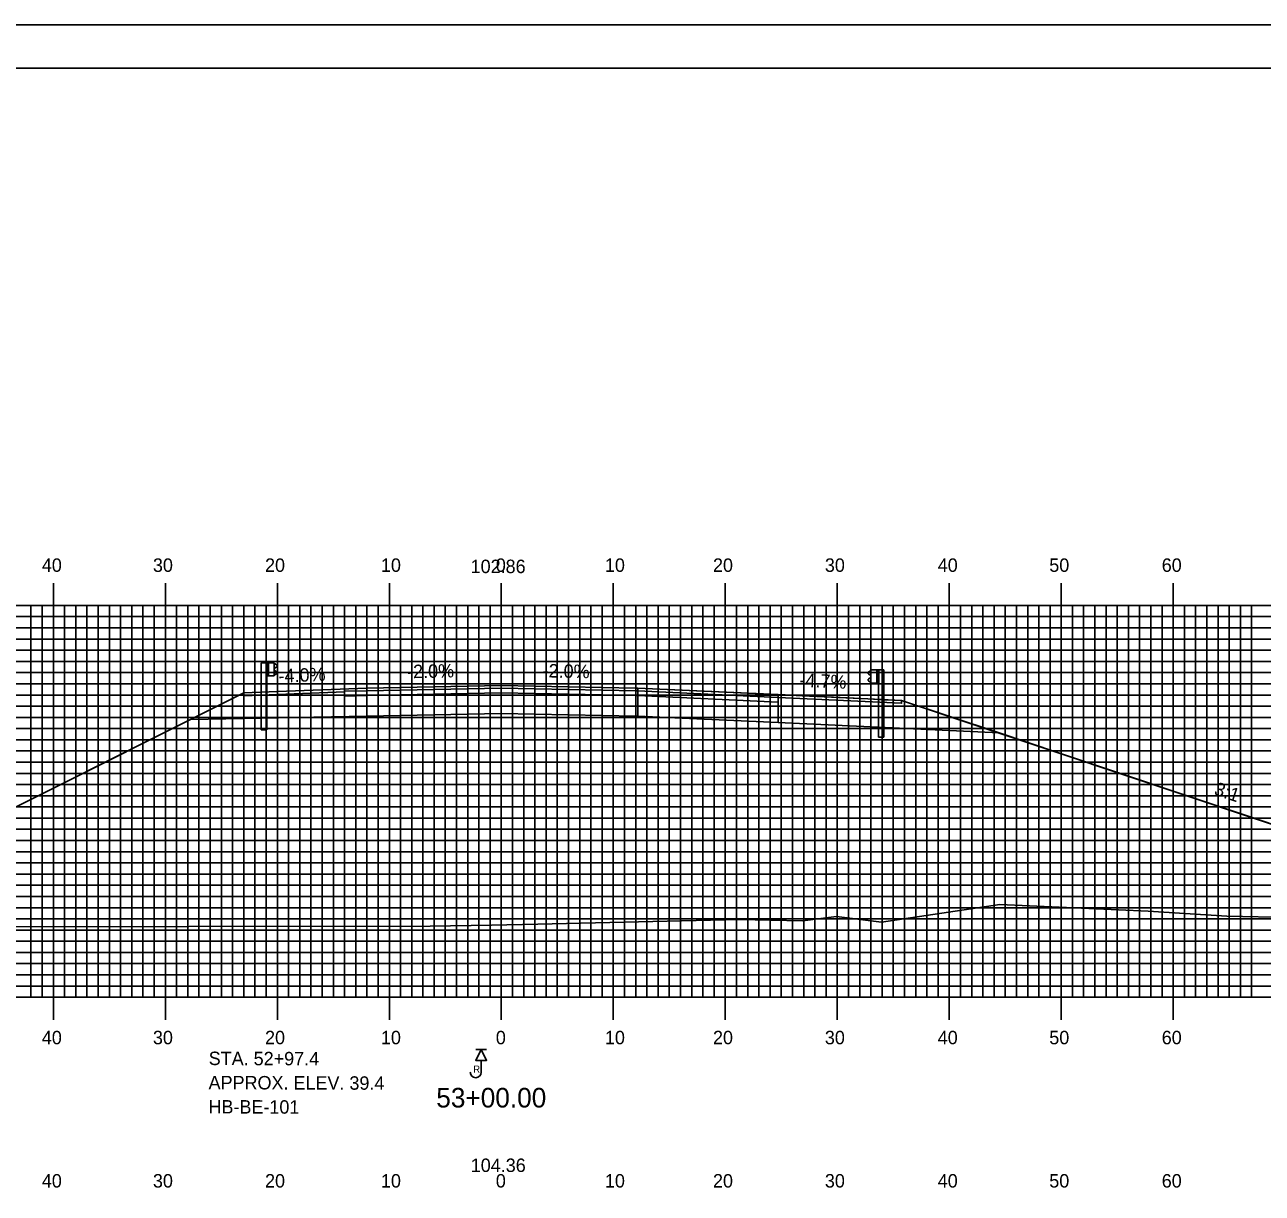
# Model space of a CAD drawing. Extents: x 1755888 to 1756232, y 442591 to 442811.
# Drawn here: x 1756011.5 to 1756122, y 442706.2 to 442810.5 of the extents above; entities that cross this region are included whole.
import ezdxf

# ---------------------------------------------------------------- set-up
doc = ezdxf.new("R2010")
doc.units = 0
for name, color, linetype in [('ANNOTATION', 7, 'Continuous'), ('BORDER', 7, 'Continuous'), ('BORING - REFUSAL', 7, 'Continuous'), ('D_Guardrail_Beam_Lt', 7, 'Continuous'), ('D_Guardrail_Beam_Rt', 7, 'Continuous'), ('D_Roadway_Centerline', 7, 'Continuous'), ('D_Roadway_Centerline_Text', 7, 'Continuous'), ('D_Roadway_Edge_Shoulder', 7, 'Continuous'), ('D_Roadway_Edge_TW', 7, 'Continuous'), ('D_Roadway_Pavement', 7, 'Continuous'), ('D_Roadway_SlopeLines', 7, 'Continuous'), ('D_Roadway_SubGrade', 7, 'Continuous'), ('H_V ANNOTATION', 7, 'Continuous'), ('MAJOR', 7, 'Continuous'), ('MINOR', 7, 'Continuous'), ('PLOT BOUNDARY', 7, 'Continuous'), ('S_Roadway_Centerline', 7, 'Continuous')]:
    doc.layers.add(name, color=color, linetype=linetype)

msp = doc.modelspace()

# ---------------------------------------------------------------- linework, layer by layer
at = {"layer": 'BORDER'}
msp.add_lwpolyline([(1755904.46, 442596.67), (1756224.46, 442596.67), (1756224.46, 442806.67), (1755904.46, 442806.67)], close=True, dxfattribs=at)
at = {"layer": 'BORING - REFUSAL'}
for p, q in [((1756052.74, 442718.99), (1756051.78, 442718.99)), ((1756052.26, 442718.03), (1756052.26, 442716.97))]:
    msp.add_line(p, q, dxfattribs=at)
msp.add_lwpolyline([(1756052.26, 442718.99), (1756052.74, 442718.03), (1756051.78, 442718.03)], close=True, dxfattribs=at)
msp.add_arc((1756051.77, 442716.97), 0.485, 180, 0, dxfattribs=at)
at = {"layer": 'D_Guardrail_Beam_Lt'}
for p, q in [((1756032.63, 442753.55), (1756032.63, 442747.55)), ((1756033.1, 442753.55), (1756032.63, 442753.55)), ((1756033.79, 442753.55), (1756033.1, 442753.55)), ((1756033.1, 442753.55), (1756033.1, 442752.38)), ((1756033.16, 442753.55), (1756033.16, 442752.38)), ((1756033.27, 442753.55), (1756033.27, 442752.38)), ((1756033.79, 442752.38), (1756033.79, 442753.55)), ((1756033.79, 442753.47), (1756033.86, 442753.45)), ((1756034.02, 442753.2), (1756033.82, 442753.07)), ((1756033.88, 442753.45), (1756034.02, 442753.35)), ((1756033.1, 442752.38), (1756033.79, 442752.38)), ((1756033.12, 442747.55), (1756033.12, 442752.38)), ((1756033.79, 442753), (1756033.79, 442752.93)), ((1756033.86, 442752.48), (1756033.79, 442752.47)), ((1756033.82, 442752.87), (1756034.02, 442752.73)), ((1756034.02, 442752.59), (1756033.88, 442752.49)), ((1756033.12, 442747.55), (1756032.63, 442747.55))]:
    msp.add_line(p, q, dxfattribs=at)
for centre, major_axis, start_param, end_param in [((1756033.87, 442753), (-0.0789, 0), 5.323254, 6.283185), ((1756033.85, 442753.41), (0.0417, 0), 0.959931, 1.376053), ((1756033.97, 442753.28), (0.0877, 0), 5.323254, 7.243116), ((1756033.87, 442752.93), (-0.0789, 0), 6.283185, 7.243116), ((1756033.85, 442752.52), (0.0417, 0), 4.907132, 5.323254), ((1756033.97, 442752.66), (0.0877, 0), 5.323254, 7.243116)]:
    msp.add_ellipse(centre, major_axis=major_axis, ratio=0.995501, start_param=start_param, end_param=end_param, dxfattribs=at)
at = {"layer": 'D_Guardrail_Beam_Rt'}
for p, q in [((1756086.98, 442752.8), (1756086.84, 442752.7)), ((1756086.84, 442752.56), (1756087.03, 442752.42)), ((1756087.03, 442752.23), (1756086.84, 442752.09)), ((1756086.84, 442751.95), (1756086.98, 442751.85)), ((1756087.07, 442752.82), (1756086.99, 442752.81)), ((1756087.06, 442752.36), (1756087.06, 442752.29)), ((1756087.07, 442752.91), (1756087.76, 442752.91)), ((1756087.07, 442751.74), (1756087.07, 442752.91)), ((1756087.59, 442752.91), (1756087.59, 442751.74)), ((1756087.69, 442752.91), (1756087.69, 442751.74)), ((1756087.76, 442752.91), (1756088.23, 442752.91)), ((1756087.76, 442752.91), (1756087.76, 442751.74)), ((1756088.23, 442752.91), (1756088.23, 442746.91)), ((1756086.99, 442751.84), (1756087.07, 442751.82)), ((1756087.76, 442751.74), (1756087.07, 442751.74)), ((1756087.74, 442746.91), (1756087.74, 442751.74)), ((1756087.74, 442746.91), (1756088.23, 442746.91))]:
    msp.add_line(p, q, dxfattribs=at)
for centre, major_axis, start_param, end_param in [((1756086.89, 442752.63), (-0.0877, 0), 5.323254, 7.243116), ((1756086.89, 442752.02), (-0.0877, 0), 5.323254, 7.243116), ((1756087, 442752.77), (-0.0417, 0), 4.907132, 5.323254), ((1756086.99, 442752.36), (0.0789, 0), 0, 0.959931), ((1756086.99, 442752.29), (0.0789, 0), 5.323254, 6.283185), ((1756087, 442751.88), (-0.0417, 0), 0.959931, 1.376053)]:
    msp.add_ellipse(centre, major_axis=major_axis, ratio=0.995501, start_param=start_param, end_param=end_param, dxfattribs=at)
at = {"layer": 'D_Roadway_Centerline'}
msp.add_lwpolyline([(1755989.06, 442729.85), (1756026.31, 442748.47), (1756031.06, 442750.85), (1756034.06, 442750.97), (1756042.06, 442751.29), (1756054.06, 442751.53), (1756066.06, 442751.29), (1756066.24, 442751.28), (1756076.73, 442750.8), (1756078.79, 442750.7), (1756080.93, 442750.6), (1756086.8, 442750.32), (1756088.3, 442750.25), (1756089.8, 442750.18), (1756096.45, 442747.96), (1756098.5, 442747.28), (1756103.73, 442745.53), (1756120.4, 442739.96), (1756133.71, 442735.51), (1756138.61, 442733.87), (1756146.45, 442731.25)], dxfattribs=at)
at = {"layer": 'D_Roadway_Edge_Shoulder'}
for points in [[(1756042.06, 442751.29), (1756034.06, 442750.97), (1756034.06, 442750.97), (1756031.06, 442750.85), (1756031.06, 442750.6), (1756040.06, 442750.96), (1756040.06, 442751), (1756042.06, 442751.04)], [(1756078.79, 442750.7), (1756086.8, 442750.32), (1756086.8, 442750.32), (1756089.8, 442750.18), (1756089.8, 442749.93), (1756078.79, 442750.45)]]:
    msp.add_lwpolyline(points, close=True, dxfattribs=at)
at = {"layer": 'D_Roadway_Edge_TW'}
for points in [[(1756042.06, 442751.04), (1756042.06, 442751.29), (1756054.06, 442751.53), (1756066.06, 442751.29), (1756066.06, 442751.04), (1756054.06, 442751.28)], [(1756066.06, 442751.29), (1756066.24, 442751.28), (1756066.24, 442751.03), (1756066.06, 442751.04)], [(1756066.24, 442751.28), (1756078.79, 442750.7), (1756078.79, 442750.45), (1756066.24, 442751.03)]]:
    msp.add_lwpolyline(points, close=True, dxfattribs=at)
at = {"layer": 'D_Roadway_Pavement'}
for points in [[(1756042.06, 442751.04), (1756040.06, 442751), (1756040.06, 442750.96), (1756040.06, 442750.58), (1756042.06, 442750.62)], [(1756042.06, 442750.62), (1756042.06, 442751.04), (1756054.06, 442751.28), (1756066.06, 442751.04), (1756066.06, 442750.62), (1756054.06, 442750.86)], [(1756066.06, 442751.04), (1756066.24, 442751.03), (1756066.24, 442750.62), (1756066.06, 442750.62)], [(1756066.24, 442751.03), (1756078.79, 442750.45), (1756078.79, 442750.03), (1756066.24, 442750.62)]]:
    msp.add_lwpolyline(points, close=True, dxfattribs=at)
msp.add_lwpolyline([(1756078.79, 442750.45), (1756078.79, 442750.03)], dxfattribs=at)
msp.add_lwpolyline([(1756078.79, 442750.45), (1756078.79, 442750.03)], dxfattribs=at)
at = {"layer": 'D_Roadway_SlopeLines'}
for points in [[(1756031.06, 442750.85), (1755989.06, 442729.85)], [(1756089.8, 442750.18), (1756146.45, 442731.25)]]:
    msp.add_lwpolyline(points, dxfattribs=at)
at = {"layer": 'D_Roadway_SubGrade'}
for points in [[(1756042.06, 442750.62), (1756040.06, 442750.58), (1756040.06, 442750.96), (1756031.06, 442750.6), (1756031.06, 442750.85), (1756026.31, 442748.47), (1756042.06, 442748.79)], [(1756042.06, 442748.79), (1756042.06, 442750.62), (1756054.06, 442750.86), (1756066.06, 442750.62), (1756066.06, 442748.79), (1756054.06, 442749.03)], [(1756066.06, 442750.62), (1756066.24, 442750.62), (1756066.24, 442748.78), (1756066.06, 442748.79)], [(1756066.24, 442750.62), (1756078.79, 442750.03), (1756078.79, 442748.2), (1756066.24, 442748.78)], [(1756078.79, 442750.03), (1756078.79, 442750.45), (1756089.8, 442749.93), (1756089.8, 442750.18), (1756098.5, 442747.28), (1756078.79, 442748.2)]]:
    msp.add_lwpolyline(points, close=True, dxfattribs=at)
at = {"layer": 'MAJOR'}
for p, q in [((1756014.06, 442760.67), (1756014.06, 442758.67)), ((1756024.06, 442760.67), (1756024.06, 442758.67)), ((1756034.06, 442760.67), (1756034.06, 442758.67)), ((1756044.06, 442760.67), (1756044.06, 442758.67)), ((1756054.06, 442760.67), (1756054.06, 442758.67)), ((1756064.06, 442760.67), (1756064.06, 442758.67)), ((1756074.06, 442760.67), (1756074.06, 442758.67)), ((1756084.06, 442760.67), (1756084.06, 442758.67)), ((1756094.06, 442760.67), (1756094.06, 442758.67)), ((1756104.06, 442760.67), (1756104.06, 442758.67)), ((1756114.06, 442760.67), (1756114.06, 442758.67)), ((1755914.06, 442758.67), (1756194.06, 442758.67)), ((1755914.06, 442758.67), (1756194.06, 442758.67)), ((1756014.06, 442723.67), (1756014.06, 442758.67)), ((1756024.06, 442723.67), (1756024.06, 442758.67)), ((1756034.06, 442723.67), (1756034.06, 442758.67)), ((1756044.06, 442723.67), (1756044.06, 442758.67)), ((1756054.06, 442723.67), (1756054.06, 442758.67)), ((1756064.06, 442723.67), (1756064.06, 442758.67)), ((1756074.06, 442723.67), (1756074.06, 442758.67)), ((1756084.06, 442723.67), (1756084.06, 442758.67)), ((1756094.06, 442723.67), (1756094.06, 442758.67)), ((1756104.06, 442723.67), (1756104.06, 442758.67)), ((1756114.06, 442723.67), (1756114.06, 442758.67)), ((1755914.06, 442753.67), (1756194.06, 442753.67)), ((1755914.06, 442748.67), (1756194.06, 442748.67)), ((1755914.06, 442743.67), (1756194.06, 442743.67)), ((1755914.06, 442738.67), (1756194.06, 442738.67)), ((1755914.06, 442733.67), (1756194.06, 442733.67)), ((1755914.06, 442728.67), (1756194.06, 442728.67)), ((1755914.06, 442723.67), (1756194.06, 442723.67)), ((1755914.06, 442723.67), (1756194.06, 442723.67)), ((1756014.06, 442721.66), (1756014.06, 442723.67)), ((1756024.06, 442721.66), (1756024.06, 442723.67)), ((1756034.06, 442721.66), (1756034.06, 442723.67)), ((1756044.06, 442721.66), (1756044.06, 442723.67)), ((1756054.06, 442721.66), (1756054.06, 442723.67)), ((1756064.06, 442721.66), (1756064.06, 442723.67)), ((1756074.06, 442721.66), (1756074.06, 442723.67)), ((1756084.06, 442721.66), (1756084.06, 442723.67)), ((1756094.06, 442721.66), (1756094.06, 442723.67)), ((1756104.06, 442721.66), (1756104.06, 442723.67)), ((1756114.06, 442721.66), (1756114.06, 442723.67))]:
    msp.add_line(p, q, dxfattribs=at)
at = {"layer": 'MINOR'}
for p, q in [((1756012.06, 442723.67), (1756012.06, 442758.67)), ((1756013.06, 442723.67), (1756013.06, 442758.67)), ((1756015.06, 442723.67), (1756015.06, 442758.67)), ((1756016.06, 442723.67), (1756016.06, 442758.67)), ((1756017.06, 442723.67), (1756017.06, 442758.67)), ((1756018.06, 442723.67), (1756018.06, 442758.67)), ((1756019.06, 442723.67), (1756019.06, 442758.67)), ((1756020.06, 442723.67), (1756020.06, 442758.67)), ((1756021.06, 442723.67), (1756021.06, 442758.67)), ((1756022.06, 442723.67), (1756022.06, 442758.67)), ((1756023.06, 442723.67), (1756023.06, 442758.67)), ((1756025.06, 442723.67), (1756025.06, 442758.67)), ((1756026.06, 442723.67), (1756026.06, 442758.67)), ((1756027.06, 442723.67), (1756027.06, 442758.67)), ((1756028.06, 442723.67), (1756028.06, 442758.67)), ((1756029.06, 442723.67), (1756029.06, 442758.67)), ((1756030.06, 442723.67), (1756030.06, 442758.67)), ((1756031.06, 442723.67), (1756031.06, 442758.67)), ((1756032.06, 442723.67), (1756032.06, 442758.67)), ((1756033.06, 442723.67), (1756033.06, 442758.67)), ((1756035.06, 442723.67), (1756035.06, 442758.67)), ((1756036.06, 442723.67), (1756036.06, 442758.67)), ((1756037.06, 442723.67), (1756037.06, 442758.67)), ((1756038.06, 442723.67), (1756038.06, 442758.67)), ((1756039.06, 442723.67), (1756039.06, 442758.67)), ((1756040.06, 442723.67), (1756040.06, 442758.67)), ((1756041.06, 442723.67), (1756041.06, 442758.67)), ((1756042.06, 442723.67), (1756042.06, 442758.67)), ((1756043.06, 442723.67), (1756043.06, 442758.67)), ((1756045.06, 442723.67), (1756045.06, 442758.67)), ((1756046.06, 442723.67), (1756046.06, 442758.67)), ((1756047.06, 442723.67), (1756047.06, 442758.67)), ((1756048.06, 442723.67), (1756048.06, 442758.67)), ((1756049.06, 442723.67), (1756049.06, 442758.67)), ((1756050.06, 442723.67), (1756050.06, 442758.67)), ((1756051.06, 442723.67), (1756051.06, 442758.67)), ((1756052.06, 442723.67), (1756052.06, 442758.67)), ((1756053.06, 442723.67), (1756053.06, 442758.67)), ((1756055.06, 442723.67), (1756055.06, 442758.67)), ((1756056.06, 442723.67), (1756056.06, 442758.67)), ((1756057.06, 442723.67), (1756057.06, 442758.67)), ((1756058.06, 442723.67), (1756058.06, 442758.67)), ((1756059.06, 442723.67), (1756059.06, 442758.67)), ((1756060.06, 442723.67), (1756060.06, 442758.67)), ((1756061.06, 442723.67), (1756061.06, 442758.67)), ((1756062.06, 442723.67), (1756062.06, 442758.67)), ((1756063.06, 442723.67), (1756063.06, 442758.67)), ((1756065.06, 442723.67), (1756065.06, 442758.67)), ((1756066.06, 442723.67), (1756066.06, 442758.67)), ((1756067.06, 442723.67), (1756067.06, 442758.67)), ((1756068.06, 442723.67), (1756068.06, 442758.67)), ((1756069.06, 442723.67), (1756069.06, 442758.67)), ((1756070.06, 442723.67), (1756070.06, 442758.67)), ((1756071.06, 442723.67), (1756071.06, 442758.67)), ((1756072.06, 442723.67), (1756072.06, 442758.67)), ((1756073.06, 442723.67), (1756073.06, 442758.67)), ((1756075.06, 442723.67), (1756075.06, 442758.67)), ((1756076.06, 442723.67), (1756076.06, 442758.67)), ((1756077.06, 442723.67), (1756077.06, 442758.67)), ((1756078.06, 442723.67), (1756078.06, 442758.67)), ((1756079.06, 442723.67), (1756079.06, 442758.67)), ((1756080.06, 442723.67), (1756080.06, 442758.67)), ((1756081.06, 442723.67), (1756081.06, 442758.67)), ((1756082.06, 442723.67), (1756082.06, 442758.67)), ((1756083.06, 442723.67), (1756083.06, 442758.67)), ((1756085.06, 442723.67), (1756085.06, 442758.67)), ((1756086.06, 442723.67), (1756086.06, 442758.67)), ((1756087.06, 442723.67), (1756087.06, 442758.67)), ((1756088.06, 442723.67), (1756088.06, 442758.67)), ((1756089.06, 442723.67), (1756089.06, 442758.67)), ((1756090.06, 442723.67), (1756090.06, 442758.67)), ((1756091.06, 442723.67), (1756091.06, 442758.67)), ((1756092.06, 442723.67), (1756092.06, 442758.67)), ((1756093.06, 442723.67), (1756093.06, 442758.67)), ((1756095.06, 442723.67), (1756095.06, 442758.67)), ((1756096.06, 442723.67), (1756096.06, 442758.67)), ((1756097.06, 442723.67), (1756097.06, 442758.67)), ((1756098.06, 442723.67), (1756098.06, 442758.67)), ((1756099.06, 442723.67), (1756099.06, 442758.67)), ((1756100.06, 442723.67), (1756100.06, 442758.67)), ((1756101.06, 442723.67), (1756101.06, 442758.67)), ((1756102.06, 442723.67), (1756102.06, 442758.67)), ((1756103.06, 442723.67), (1756103.06, 442758.67)), ((1756105.06, 442723.67), (1756105.06, 442758.67)), ((1756106.06, 442723.67), (1756106.06, 442758.67)), ((1756107.06, 442723.67), (1756107.06, 442758.67)), ((1756108.06, 442723.67), (1756108.06, 442758.67)), ((1756109.06, 442723.67), (1756109.06, 442758.67)), ((1756110.06, 442723.67), (1756110.06, 442758.67)), ((1756111.06, 442723.67), (1756111.06, 442758.67)), ((1756112.06, 442723.67), (1756112.06, 442758.67)), ((1756113.06, 442723.67), (1756113.06, 442758.67)), ((1756115.06, 442723.67), (1756115.06, 442758.67)), ((1756116.06, 442723.67), (1756116.06, 442758.67)), ((1756117.06, 442723.67), (1756117.06, 442758.67)), ((1756118.06, 442723.67), (1756118.06, 442758.67)), ((1756119.06, 442723.67), (1756119.06, 442758.67)), ((1756120.06, 442723.67), (1756120.06, 442758.67)), ((1756121.06, 442723.67), (1756121.06, 442758.67)), ((1755914.06, 442757.67), (1756194.06, 442757.67)), ((1755914.06, 442756.67), (1756194.06, 442756.67)), ((1755914.06, 442755.67), (1756194.06, 442755.67)), ((1755914.06, 442754.67), (1756194.06, 442754.67)), ((1755914.06, 442752.67), (1756194.06, 442752.67)), ((1755914.06, 442751.67), (1756194.06, 442751.67)), ((1755914.06, 442750.67), (1756194.06, 442750.67)), ((1755914.06, 442749.67), (1756194.06, 442749.67)), ((1755914.06, 442747.67), (1756194.06, 442747.67)), ((1755914.06, 442746.67), (1756194.06, 442746.67)), ((1755914.06, 442745.67), (1756194.06, 442745.67)), ((1755914.06, 442744.67), (1756194.06, 442744.67)), ((1755914.06, 442742.67), (1756194.06, 442742.67)), ((1755914.06, 442741.67), (1756194.06, 442741.67)), ((1755914.06, 442740.67), (1756194.06, 442740.67)), ((1755914.06, 442739.67), (1756194.06, 442739.67)), ((1755914.06, 442737.67), (1756194.06, 442737.67)), ((1755914.06, 442736.67), (1756194.06, 442736.67)), ((1755914.06, 442735.67), (1756194.06, 442735.67)), ((1755914.06, 442734.67), (1756194.06, 442734.67)), ((1755914.06, 442732.67), (1756194.06, 442732.67)), ((1755914.06, 442731.67), (1756194.06, 442731.67)), ((1755914.06, 442730.67), (1756194.06, 442730.67)), ((1755914.06, 442729.67), (1756194.06, 442729.67)), ((1755914.06, 442727.67), (1756194.06, 442727.67)), ((1755914.06, 442726.67), (1756194.06, 442726.67)), ((1755914.06, 442725.67), (1756194.06, 442725.67)), ((1755914.06, 442724.67), (1756194.06, 442724.67))]:
    msp.add_line(p, q, dxfattribs=at)
at = {"layer": 'PLOT BOUNDARY'}
msp.add_lwpolyline([(1755888.27, 442590.55), (1756228.27, 442590.55), (1756228.27, 442810.55), (1755888.27, 442810.55)], close=True, dxfattribs=at)
at = {"layer": 'S_Roadway_Centerline'}
msp.add_lwpolyline([(1755914.06, 442729.3), (1755929.02, 442728.93), (1755936.66, 442728.91), (1755939.99, 442729.1), (1755959.43, 442728.85), (1755985.74, 442729.81), (1755998.98, 442729.96), (1756004.62, 442729.97), (1756047.7, 442730.01), (1756053.19, 442730.1), (1756057.32, 442730.2), (1756075.29, 442730.61), (1756080.95, 442730.51), (1756083.99, 442730.88), (1756088.01, 442730.38), (1756098.56, 442731.95), (1756111.81, 442731.35), (1756118.83, 442730.91), (1756130.1, 442730.66), (1756146.83, 442731.27), (1756164.74, 442730.34), (1756179.2, 442730.36), (1756189.71, 442730.46), (1756194.06, 442730.48)], dxfattribs=at)

# ---------------------------------------------------------------- texts
at = {"layer": 'ANNOTATION'}
for s, rotation, p in [('-4.0%', 2.2906, (1756034.19, 442751.77)), ('-2.0%', 1.1458, (1756045.66, 442752.16)), ('-2.0%', 358.8542, (1756057.74, 442752.25)), ('-4.7%', 357.3112, (1756080.66, 442751.42)), ('3:1', 341.5195, (1756117.63, 442741.79))]:
    msp.add_text(s, height=1.2, rotation=rotation, dxfattribs=at).set_placement(p)
at = {"layer": 'BORING - REFUSAL'}
for s, p in [('STA. 52+97.4', (1756027.93, 442717.61)), ('APPROX. ELEV. 39.4', (1756027.92, 442715.45)), ('HB-BE-101', (1756027.91, 442713.29))]:
    msp.add_text(s, height=1.2, rotation=359.8142, dxfattribs=at).set_placement(p)
msp.add_text('R', height=0.64, dxfattribs=at).set_placement((1756051.55, 442716.92))
at = {"layer": 'D_Roadway_Centerline'}
for s, p in [('C', (1756054.05, 442751.53)), ('L', (1756054.06, 442751.52))]:
    msp.add_text(s, height=0.0146, dxfattribs=at).set_placement(p)
at = {"layer": 'D_Roadway_Centerline_Text'}
for s, p in [('102.86', (1756051.32, 442761.56)), ('104.36', (1756051.33, 442708.06))]:
    msp.add_text(s, height=1.2, dxfattribs=at).set_placement(p)
at = {"layer": 'H_V ANNOTATION'}
for s, height, p in [('40', 1.2, (1756013.03, 442761.67)), ('30', 1.2, (1756022.95, 442761.67)), ('20', 1.2, (1756032.96, 442761.67)), ('10', 1.2, (1756043.31, 442761.67)), ('0', 1.2, (1756053.57, 442761.67)), ('10', 1.2, (1756063.31, 442761.67)), ('20', 1.2, (1756072.96, 442761.67)), ('30', 1.2, (1756082.95, 442761.67)), ('40', 1.2, (1756093.03, 442761.67)), ('50', 1.2, (1756102.99, 442761.67)), ('60', 1.2, (1756113.03, 442761.67)), ('40', 1.2, (1756013.03, 442719.47)), ('30', 1.2, (1756022.95, 442719.47)), ('20', 1.2, (1756032.96, 442719.47)), ('10', 1.2, (1756043.31, 442719.47)), ('0', 1.2, (1756053.57, 442719.47)), ('10', 1.2, (1756063.31, 442719.47)), ('20', 1.2, (1756072.96, 442719.47)), ('30', 1.2, (1756082.95, 442719.47)), ('40', 1.2, (1756093.03, 442719.47)), ('50', 1.2, (1756102.99, 442719.47)), ('60', 1.2, (1756113.03, 442719.47)), ('53+00.00', 1.75, (1756048.25, 442713.82)), ('40', 1.2, (1756013.03, 442706.67)), ('30', 1.2, (1756022.95, 442706.67)), ('20', 1.2, (1756032.96, 442706.67)), ('10', 1.2, (1756043.31, 442706.67)), ('0', 1.2, (1756053.57, 442706.67)), ('10', 1.2, (1756063.31, 442706.67)), ('20', 1.2, (1756072.96, 442706.67)), ('30', 1.2, (1756082.95, 442706.67)), ('40', 1.2, (1756093.03, 442706.67)), ('50', 1.2, (1756102.99, 442706.67)), ('60', 1.2, (1756113.03, 442706.67))]:
    msp.add_text(s, height=height, dxfattribs=at).set_placement(p)

doc.saveas('drawing.dxf')
